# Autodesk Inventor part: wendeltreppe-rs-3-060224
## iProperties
Created: 2006-02
Part Number: wendeltreppe-rs-3-060224
Cost Center: 0 kg
Document SubType Name: Modeling
Designer: rsc
Authority: 0 mm^3
Author: rsc
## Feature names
1. Extrusion1
2. Extrusion2
3. Rechteckige Anordnung3 [Rectangular Pattern]
4. Extrusion3
